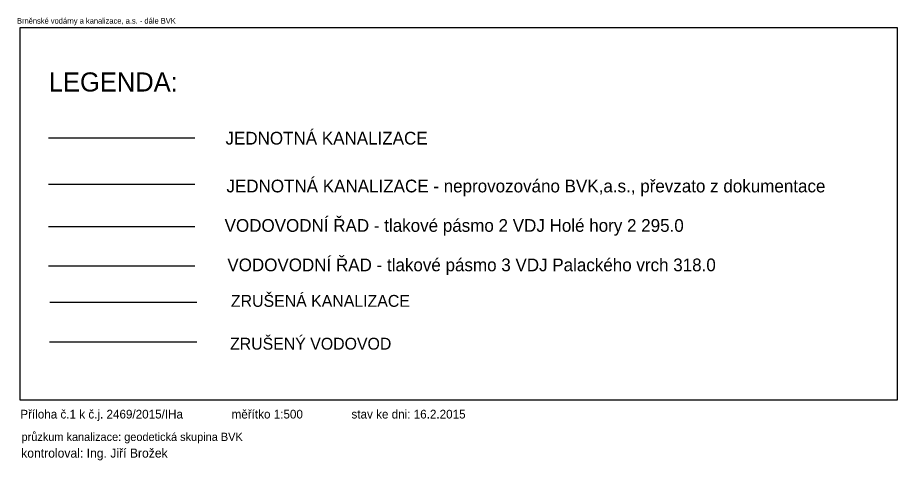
# Model space of a CAD drawing. Extents: x -599301 to -598831, y -1159041 to -1158822.
# Drawn here: x -598931 to -598831.3, y -1159021.8 to -1158971.7 of the extents above; entities that cross this region are included whole.
import ezdxf

# ---------------------------------------------------------------- set-up
doc = ezdxf.new("R2010")
doc.units = 0
for name, color, linetype in [('ft_g_20111', 7, 'Continuous'), ('Implicitní', 7, 'Continuous'), ('KJ Sběrač (ul-stoka)', 7, 'Continuous'), ('LEGENDA', 7, 'Continuous'), ('Level 62', 7, 'Continuous'), ('Level 63', 7, 'Continuous')]:
    doc.layers.add(name, color=color, linetype=linetype)

msp = doc.modelspace()

# ---------------------------------------------------------------- linework, layer by layer
at = {"layer": 'ft_g_20111'}
for points in [[(-598927.432, -1158995.284), (-598910.885, -1158995.284)], [(-598927.432, -1158999.747), (-598910.885, -1158999.747)]]:
    msp.add_lwpolyline(points, dxfattribs=at)
at = {"layer": 'Implicitní'}
for p, q in [((-598927.288, -1159003.851), (-598910.663, -1159003.851)), ((-598927.322, -1159008.353), (-598910.663, -1159008.353))]:
    msp.add_line(p, q, dxfattribs=at)
msp.add_lwpolyline([(-598930.713, -1159014.915), (-598831.281, -1159014.915), (-598831.281, -1158972.819), (-598930.713, -1158972.819)], close=True, dxfattribs=at)
at = {"layer": 'KJ Sběrač (ul-stoka)'}
msp.add_line((-598927.433, -1158990.501), (-598910.887, -1158990.501), dxfattribs=at)
at = {"layer": 'LEGENDA'}
msp.add_lwpolyline([(-598910.889, -1158985.31), (-598927.433, -1158985.31)], dxfattribs=at)

# ---------------------------------------------------------------- texts
at = {"layer": 'Implicitní'}
for s, height, p in [('JEDNOTNÁ KANALIZACE - neprovozováno BVK,a.s., převzato z dokumentace', 1.44, (-598907.29, -1158991.442)), ('VODOVODNÍ ŘAD - tlakové pásmo 2 VDJ Holé hory 2 295.0', 1.44, (-598907.496, -1158995.905)), ('VODOVODNÍ ŘAD - tlakové pásmo 3 VDJ Palackého vrch 318.0', 1.44, (-598907.186, -1159000.368)), ('ZRUŠENÁ KANALIZACE', 1.344, (-598906.781, -1159004.391)), ('ZRUŠENÝ VODOVOD', 1.344, (-598906.886, -1159009.237))]:
    msp.add_text(s, height=height, dxfattribs=at).set_placement(p)
at = {"layer": 'LEGENDA'}
for s, height, p in [('LEGENDA:', 2.16, (-598927.413, -1158980.029)), ('JEDNOTNÁ KANALIZACE', 1.44, (-598907.397, -1158986.03))]:
    msp.add_text(s, height=height, dxfattribs=at).set_placement(p)
at = {"layer": 'Level 62'}
for s, height, p in [('Příloha č.1 k č.j. 2469/2015/IHa               měřítko 1:500               stav ke dni: 16.2.2015', 0.98784, (-598930.643, -1159017.029)), ('průzkum kanalizace: geodetická skupina BVK', 0.9261, (-598930.502, -1159019.566)), ('kontroloval: Ing. Jiří Brožek', 1.029, (-598930.544, -1159021.455))]:
    msp.add_text(s, height=height, dxfattribs=at).set_placement(p)
at = {"layer": 'Level 63'}
msp.add_text('Brněnské vodárny a kanalizace, a.s. - dále BVK', height=0.637, dxfattribs=at).set_placement((-598931.02, -1158972.35))

doc.saveas('drawing.dxf')
